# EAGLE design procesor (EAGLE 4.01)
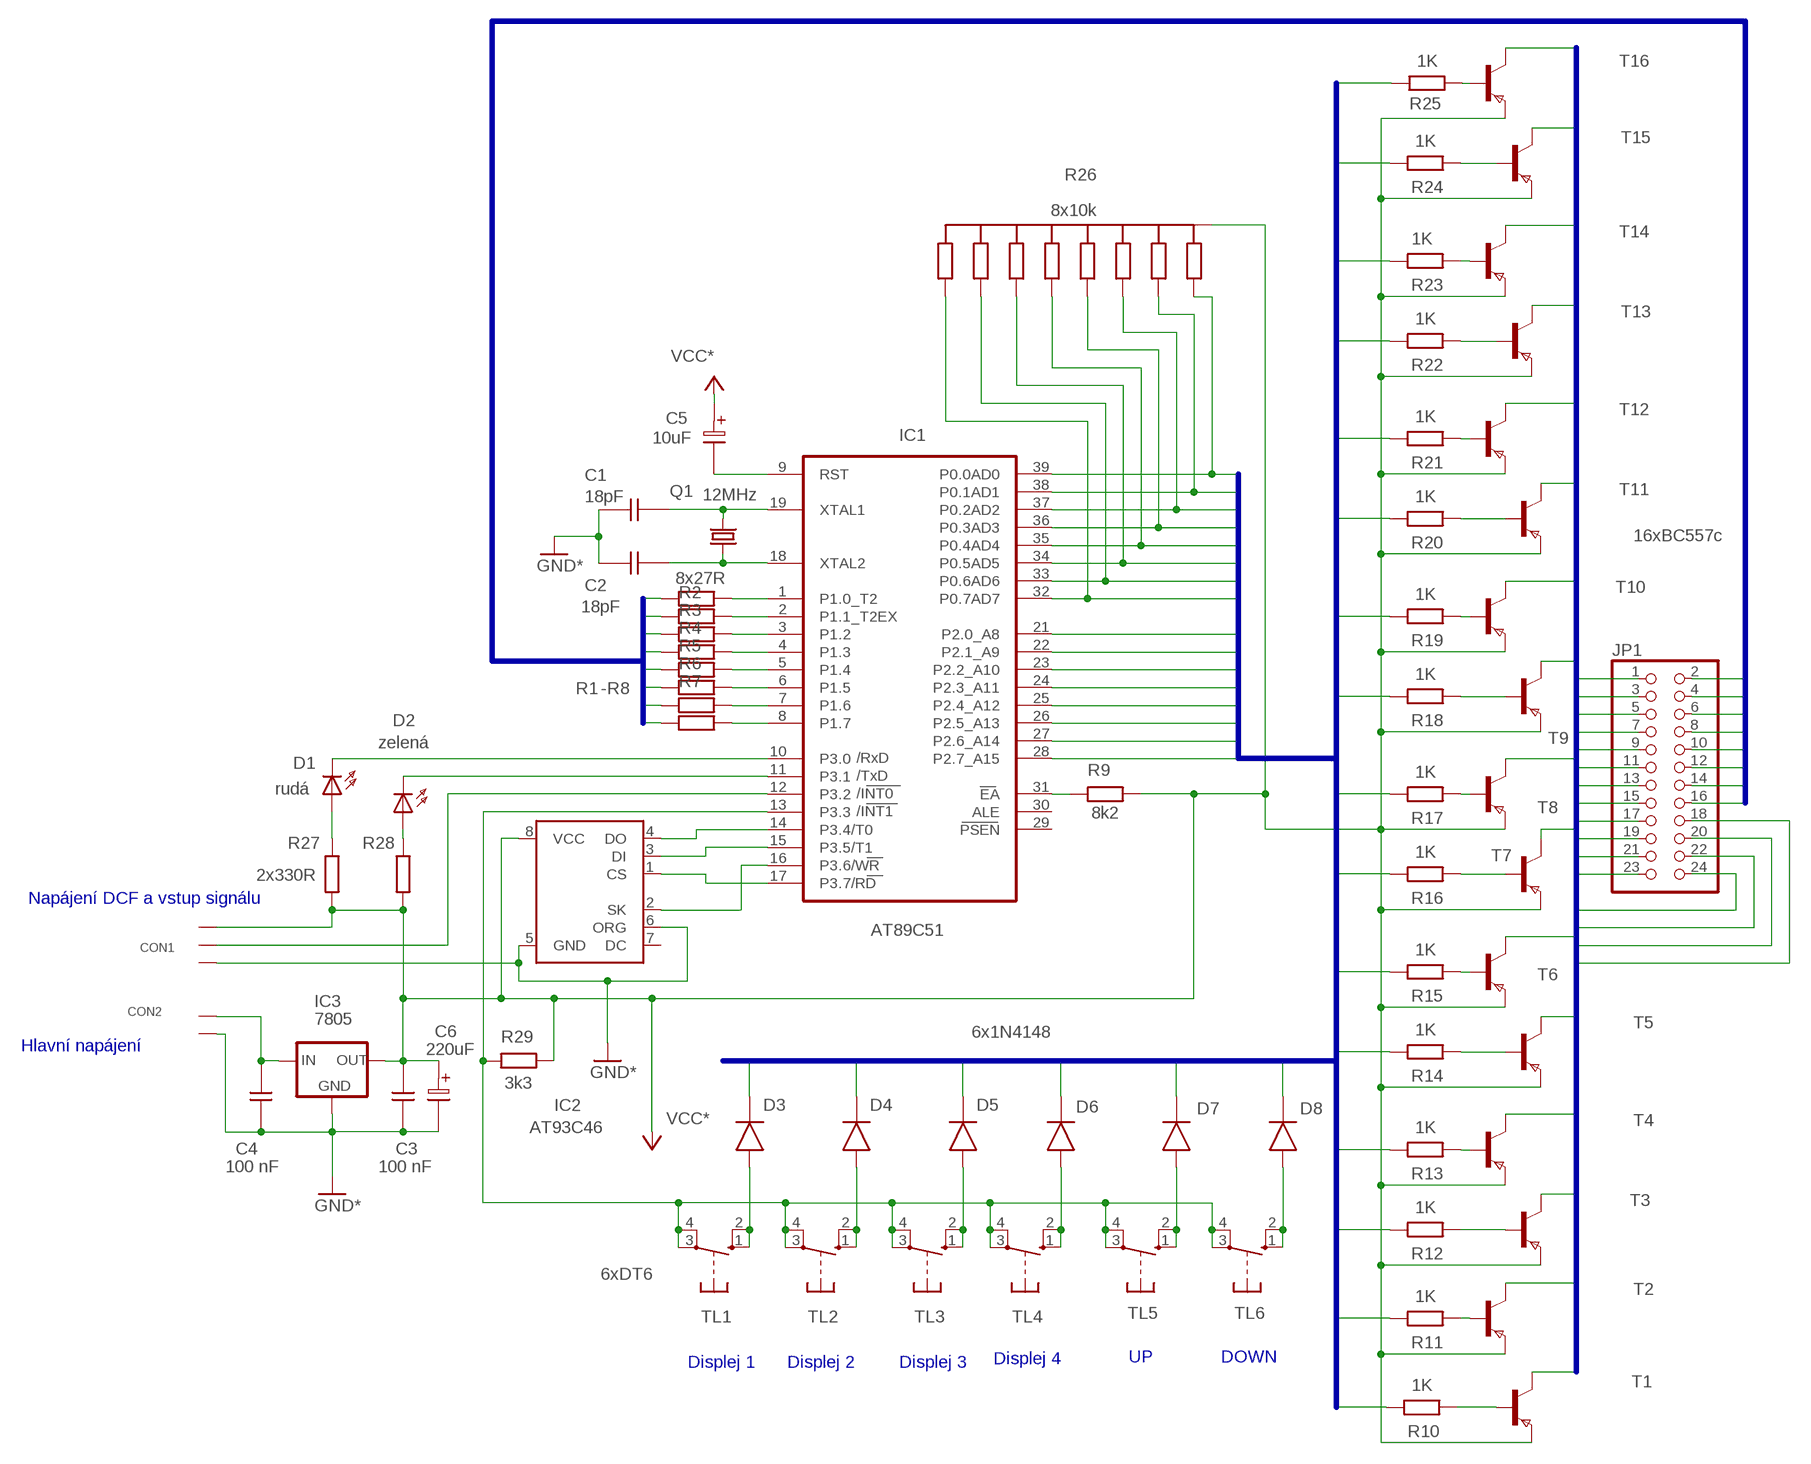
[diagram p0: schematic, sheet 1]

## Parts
-R8  RR-10  [RR-10]
C1  18pF  CK  [CK]
C2  18pF  CK  [CK]
C3  100 nF  CK  [CK]
C4  100 nF  CK  [CK]
C5  10uF  CT04  [CT04]
C6  220uF  E8X11  [E80]
CON1  ARK550/3  [ARK550/3]
CON2  ARK550/2  [ARK550/2]
D1  rudá  LED5MM  [LED5MM]
D2  zelená  LED5MM  [LED5MM]
D3  1N4148  [DO41]
D4  1N4148  [DO41]
D5  1N4148  [DO41]
D6  6x1N4148  1N4148  [DO41]
D7  1N4148  [DO41]
D8  1N4148  [DO41]
IC1  AT89C51  AT89C52P  [DIL40]
IC2  AT93C46  AT93C6P  [DIL08]
IC3  7805  78XXL  [78XXL]
JP1  PINHD-2X12  [2X12]
Q1  12MHz  HC49U-V  [HC49U-V]
R1  8x27R  RR-10  [RR-10]
R2  RR-10  [RR-10]
R3  RR-10  [RR-10]
R4  RR-10  [RR-10]
R5  RR-10  [RR-10]
R6  RR-10  [RR-10]
R7  RR-10  [RR-10]
R9  8k2  RR-10  [RR-10]
R10  1K  RR-10  [RR-10]
R11  1K  RR-10  [RR-10]
R12  1K  RR-10  [RR-10]
R13  1K  RR-10  [RR-10]
R14  1K  RR-10  [RR-10]
R15  1K  RR-10  [RR-10]
R16  1K  RR-10  [RR-10]
R17  1K  RR-10  [RR-10]
R18  1K  RR-10  [RR-10]
R19  1K  RR-10  [RR-10]
R20  1K  RR-10  [RR-10]
R21  1K  RR-10  [RR-10]
R22  1K  RR-10  [RR-10]
R23  1K  RR-10  [RR-10]
R24  1K  RR-10  [RR-10]
R25  1K  RR-10  [RR-10]
R26  8x10k  RR8X  [RR8X]
R27  2x330R  RR-10  [RR-10]
R28  RR-10  [RR-10]
R29  3k3  RR-10  [RR-10]
T1  BC557C  [TO-92C]
T2  BC557C  [TO-92C]
T3  BC557C  [TO-92C]
T4  BC557C  [TO-92C]
T5  BC557C  [TO-92C]
T6  BC557C  [TO-92C]
T7  BC557C  [TO-92C]
T8  BC557C  [TO-92C]
T9  BC557C  [TO-92C]
T10  BC557C  [TO-92C]
T11  16xBC557c  BC557C  [TO-92C]
T12  BC557C  [TO-92C]
T13  BC557C  [TO-92C]
T14  BC557C  [TO-92C]
T15  BC557C  [TO-92C]
T16  BC557C  [TO-92C]
TL1  DT6  [DT6]
TL2  DT6  [DT6]
TL3  6xDT6  DT6  [DT6]
TL4  DT6  [DT6]
TL5  DT6  [DT6]
TL6  DT6  [DT6]

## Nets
ANODY0: IC1.28(P2.7_A15) R25.2
ANODY1: IC1.27(P2.6_A14) R24.2
ANODY2: IC1.26(P2.5_A13) R23.2
ANODY3: D3.K IC1.25(P2.4_A12) R22.2
ANODY4: IC1.24(P2.3_A11) R21.2
ANODY5: IC1.23(P2.2_A10) R20.2
ANODY6: IC1.22(P2.1_A9) R19.2
ANODY7: D4.K IC1.21(P2.0_A8) R18.2
ANODY8: IC1.32(P0.7AD7) R17.2 R26.9
ANODY9: IC1.33(P0.6AD6) R16.2 R26.8
ANODY10: D8.K IC1.34(P0.5AD5) R15.2 R26.7
ANODY11: D5.K IC1.35(P0.4AD4) R14.2 R26.6
ANODY12: IC1.36(P0.3AD3) R13.2 R26.5
ANODY13: IC1.37(P0.2AD2) R12.2 R26.4
ANODY14: D7.K IC1.38(P0.1AD1) R11.2 R26.3
ANODY15: D6.K IC1.39(P0.0AD0) R10.2 R26.2
GND: C1.1 C2.1 C3.1 C4.1 C6.2 CON1.3 CON2.1 IC2.5(GND) IC2.6(ORG) IC3.GND ; supply symbol labelled GND*
N$1: IC1.1(P1.0_T2) R1.2
N$2: IC1.2(P1.1_T2EX) R2.2
N$3: IC1.3(P1.2) R3.2
N$4: IC1.4(P1.3) R4.2
N$5: IC1.5(P1.4) R5.2
N$6: IC1.6(P1.5) R6.2
N$7: IC1.7(P1.6) R7.2
N$8: -R8.2 IC1.8(P1.7)
N$9: C1.2 IC1.19(XTAL1) Q1.2
N$10: C2.2 IC1.18(XTAL2) Q1.1
N$11: D1.K(C) IC1.10(P3.0)
N$12: D2.K(C) IC1.11(P3.1)
N$13: D3.A TL1.1 TL1.2
N$14: D2.A R28.2
N$15: D1.A R27.2
N$16: IC1.15(P3.5/T1) IC2.3(DI)
N$17: IC1.14(P3.4/T0) IC2.4(DO)
N$18: CON1.2 IC1.12(P3.2)
N$19: IC1.16(P3.6/WR) IC2.2(SK)
N$20: IC1.17(P3.7/RD) IC2.1(CS)
N$22: C5.2 IC1.9(RST)
N$23: IC1.31(EA) R9.1
N$24: IC1.13(P3.3) R29.1 TL1.3 TL1.4 TL2.3 TL2.4 TL3.3 TL3.4 TL4.3 TL4.4 TL5.3 TL5.4 TL6.3 TL6.4
N$25: C4.2 CON2.2 IC3.IN
N$26: D4.A TL2.1 TL2.2
N$27: R10.1 T1.2(B)
N$28: R11.1 T2.2(B)
N$29: R12.1 T3.2(B)
N$30: D5.A TL3.1 TL3.2
N$31: R25.1 T16.2(B)
N$32: R24.1 T15.2(B)
N$33: R23.1 T14.2(B)
N$34: R22.1 T13.2(B)
N$35: R21.1 T12.2(B)
N$36: R20.1 T11.2(B)
N$37: R19.1 T10.2(B)
N$38: R18.1 T9.2(B)
N$39: R17.1 T8.2(B)
N$40: R16.1 T7.2(B)
N$41: R15.1 T6.2(B)
N$42: R14.1 T5.2(B)
N$43: R13.1 T4.2(B)
N$44: D6.A TL4.1 TL4.2
N$45: D7.A TL5.1 TL5.2
N$47: D8.A TL6.1 TL6.2
SEGMENT_KATODY0: JP1.16 R1.1
SEGMENT_KATODY1: JP1.14 R2.1
SEGMENT_KATODY2: JP1.12 R3.1
SEGMENT_KATODY3: JP1.10 R4.1
SEGMENT_KATODY4: JP1.8 R5.1
SEGMENT_KATODY5: JP1.6 R6.1
SEGMENT_KATODY6: JP1.4 R7.1
SEGMENT_KATODY7: -R8.1 JP1.2
VCC: C3.2 C5.1 C6.1 CON1.1 IC2.8(VCC) IC3.OUT R9.2 R26.1 R27.1 R28.1 R29.2 T1.1(E) T2.1(E) T3.1(E) T4.1(E) T5.1(E) T6.1(E) T7.1(E) T8.1(E) T9.1(E) T10.1(E) T11.1(E) T12.1(E) T13.1(E) T14.1(E) T15.1(E) T16.1(E) ; supply symbol labelled VCC*
VYSTUP_ANOD0: JP1.17 T16.3(C)
VYSTUP_ANOD1: JP1.19 T15.3(C)
VYSTUP_ANOD2: JP1.21 T14.3(C)
VYSTUP_ANOD3: JP1.23 T13.3(C)
VYSTUP_ANOD4: JP1.24 T12.3(C)
VYSTUP_ANOD5: JP1.22 T11.3(C)
VYSTUP_ANOD6: JP1.20 T10.3(C)
VYSTUP_ANOD7: JP1.18 T9.3(C)
VYSTUP_ANOD8: JP1.15 T8.3(C)
VYSTUP_ANOD9: JP1.13 T7.3(C)
VYSTUP_ANOD10: JP1.11 T6.3(C)
VYSTUP_ANOD11: JP1.9 T5.3(C)
VYSTUP_ANOD12: JP1.7 T4.3(C)
VYSTUP_ANOD13: JP1.5 T3.3(C)
VYSTUP_ANOD14: JP1.3 T2.3(C)
VYSTUP_ANOD15: JP1.1 T1.3(C)
Unconnected: IC1.29(PSEN) IC1.30(ALE) IC2.7(DC)

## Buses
ANODY[0..15]
SEGMENT_KATODY[0..7]
VYSTUP_ANOD[0..15]

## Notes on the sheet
- Napájení DCF a vstup signálu
- Hlavní napájení
- Displej 4 | UP | DOWN
- Displej 1 | Displej 2 | Displej 3

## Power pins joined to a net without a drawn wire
GND: IC1.20(GND)
VCC: IC1.40(VCC)

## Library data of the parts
-R8 R1-R7 R9-R25 R27-R29 = GM99:RR-10
C1-C4 = GM99:CK
C5 = GM99:CT04
C6 = GM99:E8X11
CON1 = GM99:ARK550/3
CON2 = GM99:ARK550/2
D1 D2 = led:LED5MM: LED
D3-D8 = GM99:1N4148
IC1 = atmel:AT89C52P: MICROCONTROLLER 8 Kbytes FLASH
IC2 = atmel:AT93C*6: 3-wire serial EEPROM
IC3 = v-reg:78XXL: VOLTAGE REGULATOR
JP1 = pinhead:PINHD-2X12: PIN HEADER
Q1 = crystal:HC49U-V: CRYSTAL
R26 = GM99:RR8X
T1-T16 = GM99:BC557C
TL1-TL6 = switch-misc:DT6: ITT SWITCH

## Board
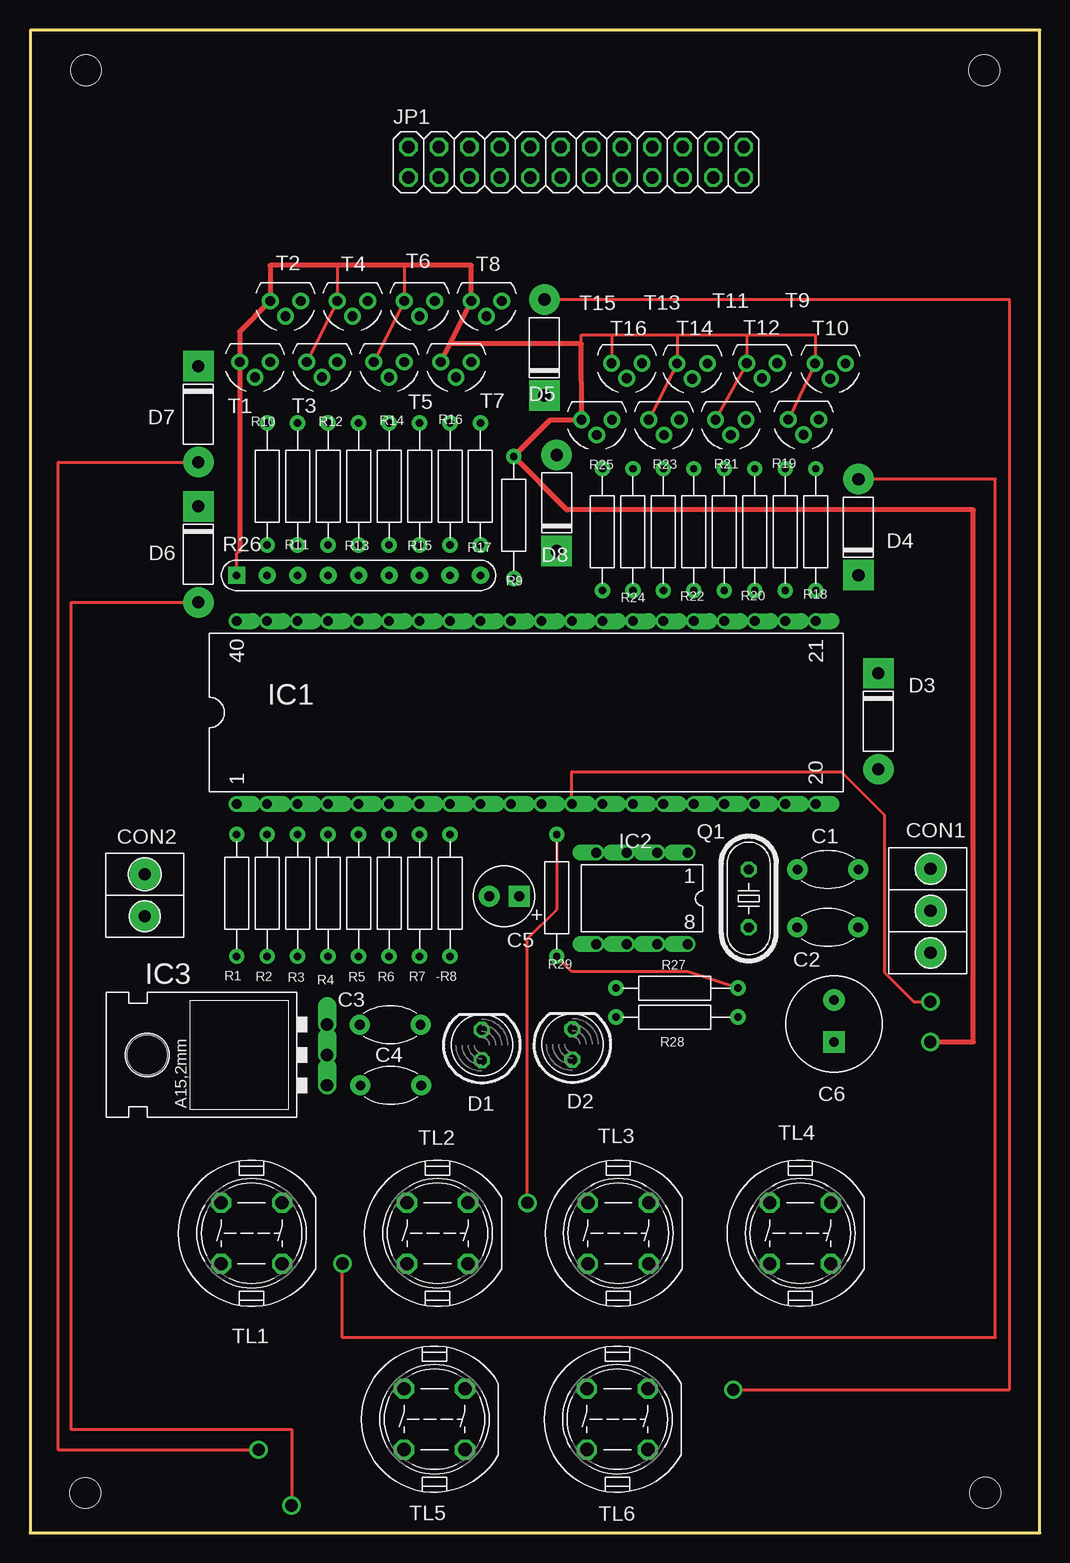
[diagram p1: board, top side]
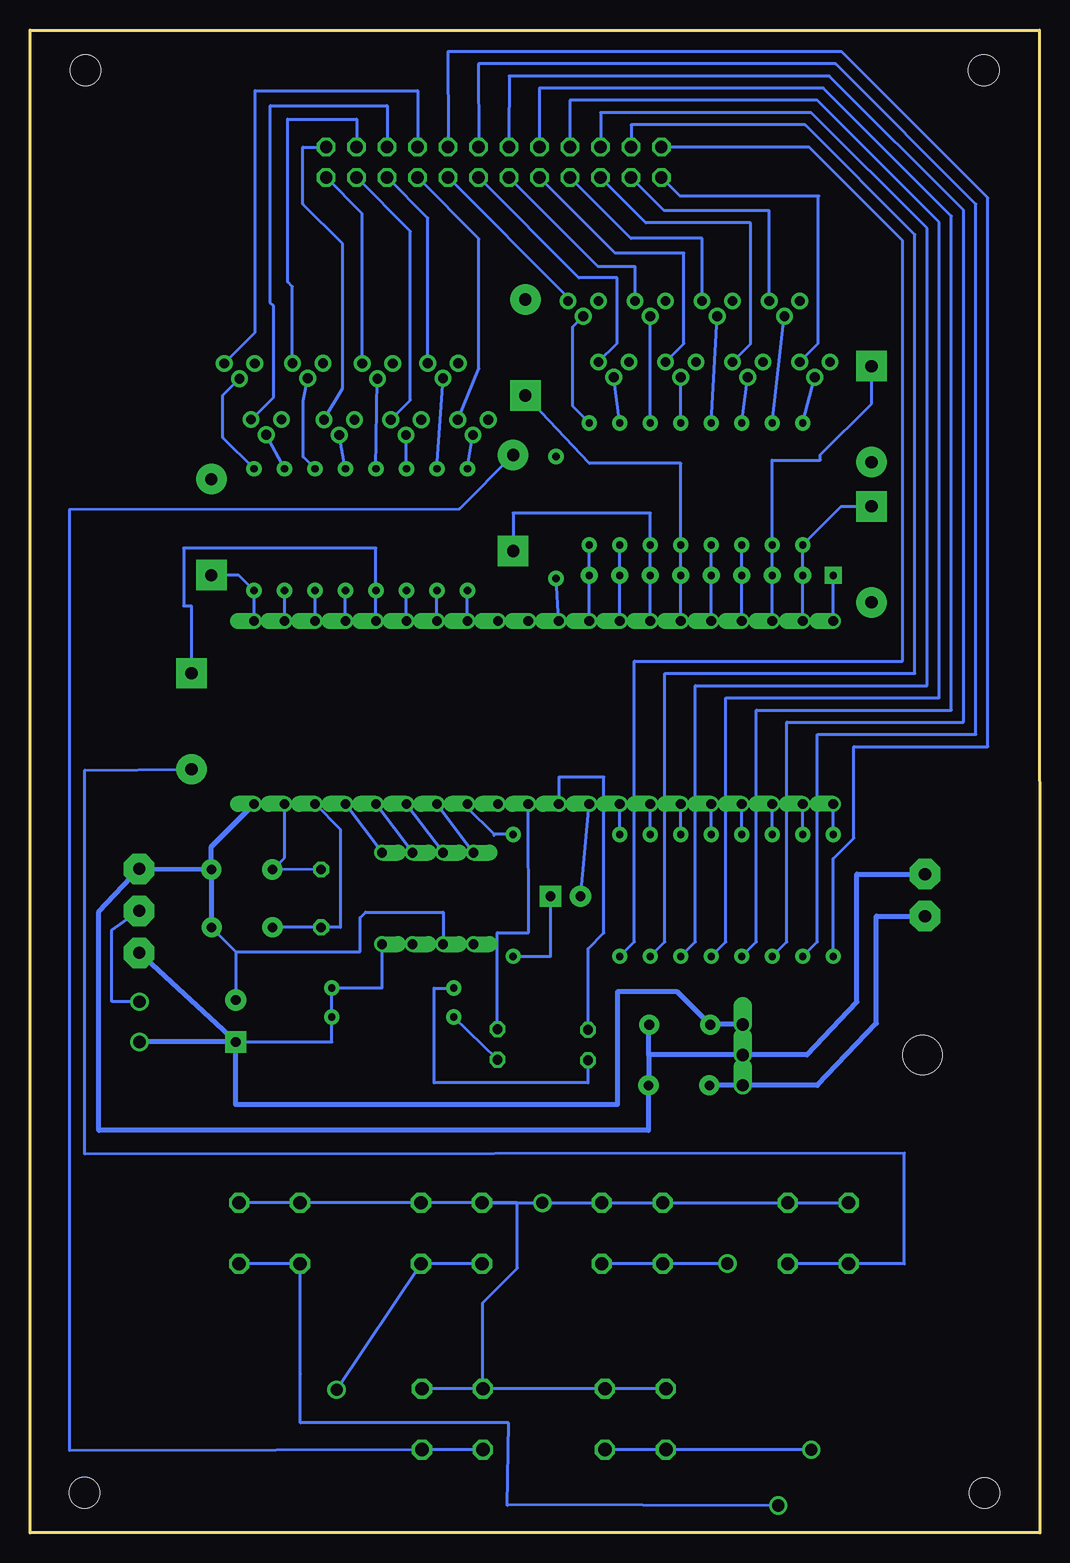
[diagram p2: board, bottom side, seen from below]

Size 84.15 x 125.25 mm. Coordinates in mm from the lower left corner, seen from the top.
Outline: 0,0 84.15,0 84.15,125.25 0.03,125.25 0,0
Copper layers used: Top, Bottom
Holes 2.54 mm at 4.6,3.33 79.6,3.35 4.67,121.89 79.53,121.89

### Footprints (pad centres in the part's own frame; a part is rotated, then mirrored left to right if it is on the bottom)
RR-10 = drill 0.61 pad 1.27 round: 1 0,0; 2 10.16,0
CK = drill 0.813 pad 1.676 round: 1 0,0; 2 5.08,0
CT04 = drill 0.813 pad 1.778 square: 1 0,0 | drill 0.813 pad 1.778 round: 2 2.5,0
E80 = drill 0.813 pad 1.778 square: 1 0,0 | drill 0.813 pad 1.778 round: 2 3.5,0
ARK550/3 = drill 1.016 pad 2.54 octagon: 1 0,0; 2 3.5,0; 3 7,0
ARK550/2 = drill 1.016 pad 2.54 octagon: 1 0,0; 2 3.5,0
LED5MM = drill 0.813 octagon: A -1.27,0; K 1.27,0
DO41 = drill 1.016 pad 2.54 round: A 8,0 | drill 1.016 pad 2.54 square: K 0,0
DIL40 = drill 0.813 offset: 1 -24.13,-7.62; 2 -21.59,-7.62; 3 -19.05,-7.62; 4 -16.51,-7.62; 5 -13.97,-7.62; 6 -11.43,-7.62; 7 -8.89,-7.62; 8 -6.35,-7.62; 9 -3.81,-7.62; 10 -1.27,-7.62; 11 1.27,-7.62; 12 3.81,-7.62; 13 6.35,-7.62; 14 8.89,-7.62; 15 11.43,-7.62; 16 13.97,-7.62; 17 16.51,-7.62; 18 19.05,-7.62; 19 21.59,-7.62; 20 24.13,-7.62; 21 24.13,7.62; 22 21.59,7.62; 23 19.05,7.62; 24 16.51,7.62; 25 13.97,7.62; 26 11.43,7.62; 27 8.89,7.62; 28 6.35,7.62; 29 3.81,7.62; 30 1.27,7.62; 31 -1.27,7.62; 32 -3.81,7.62; 33 -6.35,7.62; 34 -8.89,7.62; 35 -11.43,7.62; 36 -13.97,7.62; 37 -16.51,7.62; 38 -19.05,7.62; 39 -21.59,7.62; 40 -24.13,7.62
DIL08 = drill 0.813 offset: 1 -3.81,-3.81; 2 -1.27,-3.81; 3 1.27,-3.81; 4 3.81,-3.81; 5 3.81,3.81; 6 1.27,3.81; 7 -1.27,3.81; 8 -3.81,3.81
78XXL = drill 1.016 offset: GND 0,-3.81; IN -2.54,-3.81; OUT 2.54,-3.81 | hole 3.302: 0,11.176
2X12 = drill 1.016 octagon: 1 -13.97,-1.27; 2 -13.97,1.27; 3 -11.43,-1.27; 4 -11.43,1.27; 5 -8.89,-1.27; 6 -8.89,1.27; 7 -6.35,-1.27; 8 -6.35,1.27; 9 -3.81,-1.27; 10 -3.81,1.27; 11 -1.27,-1.27; 12 -1.27,1.27; 13 1.27,-1.27; 14 1.27,1.27; 15 3.81,-1.27; 16 3.81,1.27; 17 6.35,-1.27; 18 6.35,1.27; 19 8.89,-1.27; 20 8.89,1.27; 21 11.43,-1.27; 22 11.43,1.27; 23 13.97,-1.27; 24 13.97,1.27
HC49U-V = drill 0.813 octagon: 1 -2.413,0; 2 2.413,0
RR8X = drill 0.61 pad 1.422 square: 1 0,0 | drill 0.61 pad 1.422 round: 2 2.54,0; 3 5.08,0; 4 7.62,0; 5 10.16,0; 6 12.7,0; 7 15.24,0; 8 17.78,0; 9 20.32,0
TO-92C = drill 0.813 pad 1.397 round: 1 0,0; 2 1.27,1.27; 3 0,2.54
DT6 = drill 1.118 octagon: 1 -2.54,2.54; 2 2.54,2.54; 3 2.54,-2.54; 4 -2.54,-2.54

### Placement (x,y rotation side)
-R8  35,48.05 90 top
C1  69.03,55.29 180 top
C2  69.02,50.46 180 top
C3  32.55,42.36 180 top
C4  32.61,37.3 180 top
C5  40.77,53.06 180 top
C6  67.01,40.92 90 top
CON1  75.05,48.34 90 top
CON2  9.57,54.9 270 top
D1  37.65,40.66 90 top
D2  45.2,40.71 90 top
D3  70.69,71.64 270 top
D4  69.04,79.82 90 top
D5  42.87,94.79 90 top
D6  14.02,85.55 270 top
D7  14.02,97.24 270 top
D8  43.89,81.83 90 top
IC1  41.35,68.37 0 top
IC2  51,52.88 180 top
IC3  20.95,39.84 90 top
JP1  45.5,114.23 0 top
Q1  59.89,52.88 90 top
R1  17.22,48.05 90 top
R2  19.76,48.05 90 top
R3  22.3,48.05 90 top
R4  24.84,48.05 90 top
R5  27.38,48.05 90 top
R6  29.92,48.05 90 top
R7  32.46,48.05 90 top
R9  40.31,79.55 90 top
R10  19.76,92.5 270 top
R11  22.3,92.5 270 top
R12  24.84,92.5 270 top
R13  27.38,92.5 270 top
R14  29.92,92.5 270 top
R15  32.46,92.5 270 top
R16  35,92.5 270 top
R17  37.54,92.5 270 top
R18  65.48,88.69 270 top
R19  62.94,88.69 270 top
R20  60.4,88.69 270 top
R21  57.86,88.69 270 top
R22  55.32,88.69 270 top
R23  52.78,88.69 270 top
R24  50.24,88.69 270 top
R25  47.7,88.69 270 top
R26  17.22,79.8 0 top
R27  59,45.41 180 top
R28  59,43 180 top
R29  43.89,58.21 270 top
T1  17.47,97.58 270 top
T2  20.01,102.66 270 top
T3  23.06,97.58 270 top
T4  25.6,102.66 270 top
T5  28.65,97.58 270 top
T6  31.19,102.66 270 top
T7  34.24,97.58 270 top
T8  36.78,102.66 270 top
T9  65.42,97.46 270 top
T10  63.19,92.79 270 top
T11  59.73,97.49 270 top
T12  57.12,92.76 270 top
T13  53.92,97.46 270 top
T14  51.56,92.76 270 top
T15  48.46,97.49 270 top
T16  45.97,92.76 270 top
TL1  18.47,24.98 180 top
TL2  33.96,24.98 180 top
TL3  49.02,24.98 180 top
TL4  64.19,24.98 180 top
TL5  33.71,9.48 180 top
TL6  48.95,9.48 180 top

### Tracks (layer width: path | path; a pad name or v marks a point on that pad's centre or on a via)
ANODY0
  Bottom 0.254: R25.2 47.7,78.51 IC1.28
ANODY1
  Bottom 0.254: R24.2 | IC1.27 R24.2 | R24.2
ANODY2
  Bottom 0.254: R23.2 | IC1.26 R23.2 | R23.2
ANODY3
  Bottom 0.254: 55.32,78.56 R22.2 | IC1.25 55.32,78.56 | 55.32,78.56 | D3.K 70.69,77.27 71.35,77.27 71.35,82.07 55.32,82.07 55.32,78.56
ANODY4
  Bottom 0.254: R21.2 57.86,78.51 IC1.24
ANODY5
  Bottom 0.254: R20.2 | IC1.23 R20.2 | R20.2
ANODY6
  Bottom 0.254: R19.2 | IC1.22 R19.2 | R19.2
ANODY7
  Bottom 0.254: IC1.21 65.48,78.51 R18.2 66.76,79.82 D4.K
ANODY8
  Bottom 0.254: IC1.32 37.54,79.78 R26.9 R17.2 | R17.2 | R17.2
ANODY9
  Bottom 0.254: IC1.33 R26.8 | R26.8 | R16.2 35,82.32 R26.8
ANODY10
  Bottom 0.254: IC1.34 R26.7 | R26.7 | R26.7 R15.2 | R15.2 | R15.2 32.46,84.99 43.89,84.99 43.89,81.81 D8.K
ANODY11
  Bottom 0.254: IC1.35 29.92,79.78 R26.6 R14.2 | R14.2 | R14.2 29.92,89.13 37.54,89.13 D5.K
ANODY12
  Bottom 0.254: IC1.36 27.38,79.75 27.38,79.76 R26.5 R13.2 | R13.2 | R13.2
ANODY13
  Bottom 0.254: IC1.37 R26.4 | R26.4 | R12.2 24.84,82.32 R26.4
ANODY14
  Bottom 0.254: IC1.38 R26.3 | R26.3 | R26.3 R11.2 | R11.2 | R11.2 22.3,89.41 18.29,89.41 18.29,89.86 14.02,94.11 D7.K 14.04,97.24 D7.K
ANODY15
  Bottom 0.254: IC1.39 R26.2 | R26.2 | R26.2 R10.2 | R10.2 | D6.K 16.55,85.55 R10.2
GND
  Bottom 0.254: C1.1 | C1.1 | C2.1 69.03,50.47 69.04,50.47 67,48.44 | 67,48.44 56.64,48.44 56.64,51.28 56.19,51.74 49.73,51.74 IC2.6 | 67,48.44 C6.2 | IC2.6 IC2.5 | IC2.6 | IC2.6
  Bottom 0.406: IC1.20 69.04,57.19 C1.1 CON1.3 78.41,51.77 78.41,33.55 32.61,33.55 C4.1 32.59,37.3 32.59,39.85 | C1.1 69.03,50.47 | CON2.1 15.24,54.9 15.24,44.23 19.39,39.84 IC3.GND | IC3.GND 24.77,39.84 | IC3.GND 32.59,39.84 32.59,39.85 | 32.59,42.36 32.59,42.37 | 32.59,42.36 C3.1 | 32.59,39.85 32.59,42.36
N$1
  Bottom 0.254: IC1.1 17.22,60.73 R1.2
N$2
  Bottom 0.254: 19.76,60.73 IC1.2 | R2.2 19.76,60.73 | 19.76,60.73
N$3
  Bottom 0.254: 22.3,60.73 IC1.3 | R3.2 22.3,60.73 | 22.3,60.73
N$4
  Bottom 0.254: 24.84,60.73 IC1.4 | R4.2 24.84,60.73 | 24.84,60.73
N$5
  Bottom 0.254: IC1.5 | R5.2 IC1.5 | IC1.5
N$6
  Bottom 0.254: IC1.6 | R6.2 IC1.6 | IC1.6
N$7
  Bottom 0.254: 32.46,60.73 IC1.7 | R7.2 32.46,60.73 | 32.46,60.73
N$8
  Bottom 0.254: IC1.8 | -R8.2 IC1.8 | IC1.8
N$9
  Bottom 0.254: 63.93,55.3 C1.2 | Q1.2 63.93,55.3 | IC1.19 | IC1.19 | 63.93,55.3 62.94,56.29 IC1.19
N$10
  Bottom 0.254: IC1.18 58.27,58.62 58.27,50.47 Q1.1 63.92,50.46 C2.2
N$11
  Bottom 0.254: IC1.10 40.08,62.99 36.32,62.99 36.32,50.01 37.64,48.69 37.64,41.91 D1.K
N$12
  Bottom 0.254: D2.K 45.2,50.04 42.6,50.04 | IC1.11 | IC1.11 | 42.6,50.04 | 42.6,50.04 IC1.11
N$13
  Bottom 0.254: 15.93,22.43 | 15.93,22.43 TL1.2 | TL1.1 21.01,22.43 15.93,22.43 | D3.A 79.58,63.57 79.58,31.57 11.28,31.65 11.28,22.43 15.93,22.43
N$14
  Bottom 0.254: R28.2 48.84,42.98 45.2,39.46 D2.A
N$15
  Bottom 0.254: R27.2 50.47,45.41 50.47,37.52 37.64,37.52 D1.A | D1.A | D1.A
N$16
  Bottom 0.254: IC1.15 52.78,60.73 IC2.3
N$17
  Bottom 0.254: IC1.14 50.24,60.73 IC2.4
N$18  (via drill 1.02)
  Top 0.254: IC1.12 45.16,63.45 67.59,63.45 71.2,59.84 71.2,46.74 73.66,44.27 v75.03,44.27
  Bottom 0.254: CON1.2 77.32,50.23 77.32,44.27 v75.03,44.27
N$19
  Bottom 0.254: IC1.16 IC2.2
N$20
  Bottom 0.254: IC1.17 IC2.1
N$22
  Bottom 0.254: IC1.9 C5.2
N$23
  Bottom 0.254: R9.1 IC1.31
N$24  (via drill 1.02)
  Top 0.254: v41.45,27.51 41.45,49.51 43.89,51.94 R29.1
  Bottom 0.254: IC1.13 47.7,60.45 45.47,58.22 | R29.1 | R29.1 | TL1.3 21,27.52 21.01,27.51 TL1.4 TL2.3 | TL2.3 31.44,27.52 31.45,27.51 | TL2.4 TL2.3 | TL2.4 36.52,27.52 36.52,27.51 | 46.48,27.51 TL3.3 TL3.4 | TL2.4 TL3.3 46.48,27.51 | TL3.4 51.58,27.52 51.59,27.51 | TL3.4 TL4.3 | TL4.3 61.65,27.51 | TL4.4 TL4.3 | TL5.3 36.24,12.02 TL5.4 TL6.3 | TL6.3 46.41,19.2 43.54,22.07 43.54,27.51 | TL6.4 TL6.3 | 43.54,27.51 46.48,27.51 | 43.54,27.51 v41.45,27.51 | R29.1 45.47,58.22 | 45.47,58.22 45.47,58.14
N$25
  Bottom 0.406: CON2.2 13.62,51.4 13.62,42.48 18.54,37.3 IC3.IN 27.51,37.3 | 27.51,37.3 C4.2 | 27.51,37.3 27.51,37.29
N$26  (via drill 1.02)
  Top 0.254: D4.A 80.44,87.82 80.44,16.31 26.04,16.31 v26.04,22.45
  Bottom 0.254: TL2.2 TL2.1 | TL2.2 31.42,22.43 | TL2.2 26.04,22.43 v26.04,22.45
N$27
  Bottom 0.254: T1.2 18.75,96.29 R10.1
N$28
  Bottom 0.254: T2.2 R11.1
N$29
  Bottom 0.254: R12.1 T3.2
N$30  (via drill 1.02)
  Top 0.254: D5.A 81.64,102.79 81.64,11.94 v58.6,11.94
  Bottom 0.254: TL3.1 v58.6,11.94 | TL3.2 TL3.1 | TL3.1 51.56,22.43
N$31
  Bottom 0.254: R25.1 47.7,88.67 T16.2
N$32
  Bottom 0.254: T15.2 R24.1
N$33
  Bottom 0.254: T14.2 52.81,91.49 R23.1
N$34
  Bottom 0.254: T13.2 R22.1
N$35
  Bottom 0.254: T12.2 R21.1
N$36
  Bottom 0.254: R20.1 61.39,89.68 61.39,94.36 61.01,96.22 T11.2
N$37
  Bottom 0.254: T10.2 R19.1
N$38
  Bottom 0.254: R18.1 68.07,91.28 68.07,94.82 T9.2
N$39
  Bottom 0.254: R17.1 38.91,93.87 38.91,100.53 T8.2
N$40
  Bottom 0.254: T7.2 35.51,96.29 R16.1
N$41
  Bottom 0.254: T6.2 R15.1
N$42
  Bottom 0.254: T5.2 R14.1
N$43
  Bottom 0.254: T4.2 R13.1
N$44  (via drill 1.02)
  Top 0.254: D6.A 3.43,77.55 3.43,8.64 21.79,8.64 | 21.79,8.64 21.79,8.56 | 21.79,8.64 v21.79,2.29
  Bottom 0.254: TL4.1 | TL4.1 TL4.2 61.62,13.26 61.62,9.17 44.27,9.17 44.37,2.29 44.37,2.36 v21.79,2.29 | TL4.1 66.73,22.43
N$45  (via drill 1.02)
  Top 0.254: D7.A 2.36,89.24 2.36,6.93 v19.05,6.93
  Bottom 0.254: TL5.2 TL5.1 | TL5.2 31.14,6.94 31.14,6.93 | TL5.2 v19.06,6.94 v19.05,6.93
N$47
  Bottom 0.254: D8.A 48.35,85.37 80.85,85.29 80.85,6.87 TL6.2 TL6.1 | TL6.1 | TL6.1
SEGMENT_KATODY0
  Bottom 0.254: R1.1 17.22,56.19 15.49,57.91 15.49,65.53 4.32,65.53 4.32,111.25 16.51,123.44 49.33,123.44 49.31,116.32 | 49.31,116.32 49.31,116.31 | 49.31,116.32 | 49.31,116.31 JP1.16 | 49.31,116.31
SEGMENT_KATODY1
  Bottom 0.254: R2.1 18.54,49.27 18.54,66.55 5.33,66.55 5.33,110.74 17.02,122.43 46.79,122.43 46.77,115.7 JP1.14
SEGMENT_KATODY2
  Bottom 0.254: R3.1 21.08,49.27 21.08,67.56 6.35,67.56 6.35,110.24 17.53,121.41 44.22,121.41 44.24,116.2 44.23,116.2 JP1.12
SEGMENT_KATODY3
  Bottom 0.254: R4.1 23.62,49.27 23.62,68.58 7.37,68.58 7.37,109.73 18.03,120.4 41.7,120.4 41.7,115.88 41.7,115.89 41.69,115.88 JP1.10
SEGMENT_KATODY4
  Bottom 0.254: R5.1 26.16,49.27 26.16,69.6 8.38,69.6 8.38,109.22 18.54,119.38 39.17,119.38 39.17,115.5 | 39.17,115.5 39.17,115.49 | 39.17,115.5 JP1.8
SEGMENT_KATODY5
  Bottom 0.254: R6.1 28.7,49.27 28.7,70.61 9.4,70.61 9.4,108.71 19.05,118.36 36.6,118.36 JP1.6 | JP1.6 | JP1.6
SEGMENT_KATODY6
  Bottom 0.254: R7.1 31.24,49.27 31.24,71.63 10.41,71.63 10.41,108.2 19.56,117.35 34.06,117.35 JP1.4 | JP1.4 | JP1.4
SEGMENT_KATODY7
  Bottom 0.254: -R8.1 33.78,49.27 33.78,72.64 11.43,72.64 11.43,107.7 19.23,115.49 JP1.2 | JP1.2 31.55,115.49 | JP1.2
VCC  (via drill 1.02)
  Top 0.254: 25.6,105.64 T4.1 T3.1 | 31.19,105.64 T6.1 T5.1 | T7.1 | 35,99.08 T8.1 | 43.36,92.76 | 45.95,99.08 45.95,99.85 48.46,99.85 | T15.1 48.46,99.85 | 48.46,99.85 53.9,99.85 | 53.9,99.85 53.92,99.85 T13.1 T14.1 | 53.9,99.85 59.72,99.85 | 59.72,99.85 59.73,99.85 T11.1 T12.1 | 59.72,99.85 65.42,99.85 T9.1 T10.1 | R29.2 45.15,46.79 54.81,46.79 R27.1 | 17.47,81.87 17.22,81.61 | 19.9,102.55 19.89,102.54 | 19.9,102.55 | T2.1 | T2.1 19.9,102.55 | 17.22,81.64 17.22,81.61 | R26.1 17.22,81.61
  Top 0.406: T2.1 20.01,105.64 25.6,105.64 31.19,105.64 36.78,105.64 T8.1 T7.1 | 35,99.08 45.95,99.08 T16.1 43.36,92.76 | 43.36,92.76 R9.2 44.75,85.27 78.61,85.27 78.61,40.92 v75.03,40.92 | 19.9,102.55 17.47,100.12 T1.1 17.47,81.87
  Bottom 0.254: C5.1 40.77,48.06 43.77,48.05 R29.2 | IC2.8 54.81,45.41 R27.1 | R27.1 | R28.1 R27.1 | R28.1 59,42.98 59.03,42.98 | R28.1 59,40.92 C6.1 | R26.1 17.22,79.78 IC1.40
  Bottom 0.406: C6.1 CON1.1 | C6.1 67,35.69 35.2,35.69 35.2,45.09 30.2,45.09 C3.2 27.47,42.38 IC3.OUT | C6.1 v75.03,40.92
VYSTUP_ANOD0
  Bottom 0.254: JP1.17 46.74,107.84 46.74,97.03 48.51,92.71 T16.3
VYSTUP_ANOD1
  Bottom 0.254: T15.3 51,109.57 JP1.19
VYSTUP_ANOD2
  Bottom 0.254: JP1.21 52.45,108.47 52.45,94.41 T14.3 | T14.3 | T14.3
VYSTUP_ANOD3
  Bottom 0.254: T13.3 56.46,109.95 JP1.23
VYSTUP_ANOD4
  Bottom 0.254: JP1.24 61.42,115.5 61.42,110.74 58.09,107.42 58.09,95.38 T12.3
VYSTUP_ANOD5
  Bottom 0.254: JP1.22 56.93,117.83 62.69,117.83 62.69,104.27 62.28,103.86 T11.3
VYSTUP_ANOD6
  Bottom 0.254: JP1.20 54.39,118.95 64.11,118.95 64.11,102.51 63.86,102.26 63.86,94.66 T10.3
VYSTUP_ANOD7
  Bottom 0.254: JP1.18 51.85,120.19 65.38,120.19 65.38,100.05 T9.3 | T9.3 | T9.3
VYSTUP_ANOD8
  Bottom 0.254: JP1.15 39.32,102.97 T8.3
VYSTUP_ANOD9
  Bottom 0.254: JP1.13 38.41,104.6 35.23,104.6 35.23,99.14 T7.3
VYSTUP_ANOD10
  Bottom 0.254: JP1.11 36.81,105.54 33.73,105.54 T6.3
VYSTUP_ANOD11
  Bottom 0.254: JP1.9 35.39,106.66 29.67,106.66 29.67,99.11 T5.3
VYSTUP_ANOD12
  Bottom 0.254: JP1.7 34.07,107.87 28.14,107.87 T4.3
VYSTUP_ANOD13
  Bottom 0.254: JP1.5 32.83,109.17 24.11,109.17 24.11,99.08 T3.3
VYSTUP_ANOD14
  Bottom 0.254: JP1.3 31.3,110.19 22.55,110.19 T2.3
VYSTUP_ANOD15
  Bottom 0.254: JP1.1 29.98,111.4 18.47,111.4 | 18.47,111.4 18.41,111.4 | T1.3 18.47,99.14 18.47,111.4

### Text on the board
Top: Strana soucastek
Bottom: Strana spoju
